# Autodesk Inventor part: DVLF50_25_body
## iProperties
Created: 2010-03
Part Number: DVLF50_25_body
Document SubType Name: Modeling
Designer: TB
Mass: 548.636 g
Surface Area: 1083.4 cm^2
Volume: 548.636 cm^3
Density: 1 g/cm^3
Author: TB
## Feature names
1. Kropp [Revolution]
2. Chamfer
3. Extrusion2
4. Hole1
5. Revolution2
6. Hole2
7. Fillet1
8. Extrusion3
9. Hole3
